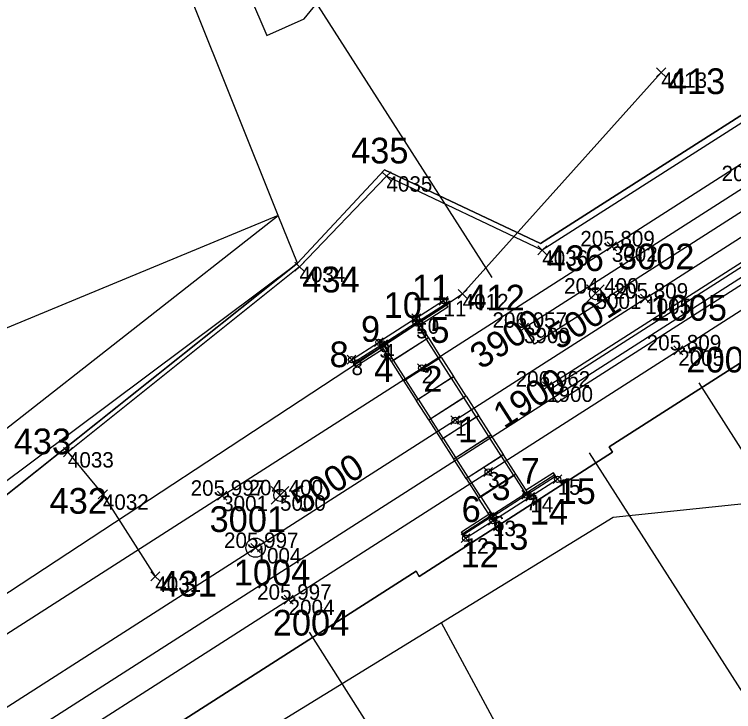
# Model space of a CAD drawing. Extents: x -752184 to -751416, y -1028299 to -1027836.
# Drawn here: x -751731.7 to -751675.7, y -1028071.5 to -1028017.3 of the extents above; entities that cross this region are included whole.
import ezdxf

# ---------------------------------------------------------------- set-up
doc = ezdxf.new("R2010")
doc.units = 0
for name, color, linetype in [('03_Staničení', 7, 'Continuous'), ('_SO 201 Nástupiště - Přesunutá', 7, 'Continuous'), ('SO 101 - spodní stavba', 7, 'Continuous'), ('SO 101 - vytyčovací body popis', 7, 'Continuous'), ('SO 101 - úpravy', 7, 'Continuous'), ('SO 101 Vytyčovací body', 7, 'Continuous'), ('SO 201 Osa koleje', 7, 'Continuous'), ('SO 201 Popisy', 7, 'Continuous'), ('SO 201 Staničení', 7, 'Continuous'), ('SO 201 Vytyčovací body', 7, 'Continuous'), ('SO 401 a 402 Přeložka SSZT a ČDT', 7, 'Continuous'), ('SO 401 a 402 Vytyčovací body', 7, 'Continuous'), ('SO 403 Přeložka SEE', 7, 'Continuous'), ('SO 403 Vytyčovací body', 7, 'Continuous'), ('Vrstva 53', 7, 'Continuous'), ('Vrstva 55', 7, 'Continuous'), ('Vrstva 60', 7, 'Continuous'), ('Vrstva 61', 7, 'Continuous'), ('Vrstva 63', 7, 'Continuous')]:
    doc.layers.add(name, color=color, linetype=linetype)

msp = doc.modelspace()

# ---------------------------------------------------------------- linework, layer by layer
at = {"layer": '03_Staničení'}
msp.add_circle((-751712.882, -1028058.77), 0.75, dxfattribs=at)
at = {"layer": '_SO 201 Nástupiště - Přesunutá'}
for p, q in [((-751690.026, -1028046.487), (-751567.868, -1027968.369)), ((-751567.232, -1027969.364), (-751689.391, -1028047.481)), ((-751652.107, -1028017.965), (-751691.168, -1028042.944)), ((-751691.987, -1028041.663), (-751674.155, -1028030.26)), ((-751691.168, -1028042.944), (-751691.987, -1028041.663)), ((-751689.391, -1028047.481), (-751690.188, -1028046.234))]:
    msp.add_line(p, q, dxfattribs=at)
msp.add_lwpolyline([(-751690.188, -1028046.234), (-751671.558, -1028034.321), (-751650.497, -1028020.852), (-751629.435, -1028007.384), (-751608.373, -1027993.915), (-751587.311, -1027980.447), (-751568.029, -1027968.117)], dxfattribs=at)
at = {"layer": 'SO 101 - spodní stavba'}
for p, q in [((-751698.251, -1028039.567), (-751700.357, -1028040.914)), ((-751698.089, -1028039.82), (-751700.195, -1028041.167)), ((-751700.141, -1028041.251), (-751698.035, -1028039.904)), ((-751698.035, -1028039.904), (-751698.251, -1028039.567)), ((-751700.357, -1028040.914), (-751700.141, -1028041.251)), ((-751703.144, -1028043.053), (-751705.25, -1028044.4)), ((-751702.146, -1028044.195), (-751702.314, -1028044.303)), ((-751702.314, -1028044.303), (-751701.355, -1028045.802)), ((-751701.187, -1028045.695), (-751702.146, -1028044.195)), ((-751701.355, -1028045.802), (-751701.187, -1028045.695)), ((-751701.176, -1028045.711), (-751701.344, -1028045.819)), ((-751701.344, -1028045.819), (-751700.385, -1028047.319)), ((-751700.217, -1028047.211), (-751701.176, -1028045.711)), ((-751700.385, -1028047.319), (-751700.217, -1028047.211)), ((-751700.206, -1028047.228), (-751700.375, -1028047.336)), ((-751699.247, -1028048.727), (-751700.206, -1028047.228)), ((-751700.375, -1028047.336), (-751699.415, -1028048.835)), ((-751699.415, -1028048.835), (-751699.247, -1028048.727)), ((-751699.236, -1028048.744), (-751699.405, -1028048.852)), ((-751699.405, -1028048.852), (-751698.446, -1028050.351)), ((-751698.277, -1028050.244), (-751699.236, -1028048.744)), ((-751698.446, -1028050.351), (-751698.277, -1028050.244)), ((-751698.266, -1028050.261), (-751698.435, -1028050.368)), ((-751698.435, -1028050.368), (-751697.476, -1028051.868)), ((-751697.307, -1028051.76), (-751698.266, -1028050.261)), ((-751697.476, -1028051.868), (-751697.307, -1028051.76)), ((-751697.297, -1028051.777), (-751697.465, -1028051.885)), ((-751696.337, -1028053.276), (-751697.297, -1028051.777)), ((-751697.465, -1028051.885), (-751696.506, -1028053.384)), ((-751696.506, -1028053.384), (-751696.337, -1028053.276)), ((-751696.327, -1028053.293), (-751696.495, -1028053.401)), ((-751696.495, -1028053.401), (-751695.536, -1028054.901)), ((-751695.368, -1028054.793), (-751696.327, -1028053.293)), ((-751689.587, -1028053.113), (-751691.693, -1028054.46)), ((-751691.639, -1028054.545), (-751689.533, -1028053.198)), ((-751691.477, -1028054.797), (-751689.371, -1028053.45)), ((-751689.371, -1028053.45), (-751689.587, -1028053.113)), ((-751691.714, -1028054.474), (-751694.62, -1028056.333)), ((-751691.498, -1028054.811), (-751691.714, -1028054.474)), ((-751691.693, -1028054.46), (-751691.477, -1028054.797)), ((-751695.536, -1028054.901), (-751695.368, -1028054.793)), ((-751694.405, -1028056.67), (-751691.498, -1028054.811)), ((-751694.641, -1028056.346), (-751696.747, -1028057.693)), ((-751694.587, -1028056.43), (-751696.693, -1028057.777)), ((-751696.532, -1028058.03), (-751694.426, -1028056.683)), ((-751694.426, -1028056.683), (-751694.641, -1028056.346)), ((-751694.62, -1028056.333), (-751694.405, -1028056.67)), ((-751696.747, -1028057.693), (-751696.532, -1028058.03))]:
    msp.add_line(p, q, dxfattribs=at)
for points in [[(-751698.035, -1028039.904), (-751697.927, -1028040.073), (-751700.054, -1028041.433)], [(-751703.284, -1028042.786), (-751703.069, -1028043.123), (-751700.162, -1028041.265), (-751700.378, -1028040.928), (-751703.284, -1028042.786)], [(-751700.216, -1028041.18), (-751700.385, -1028041.288), (-751702.954, -1028042.931), (-751703.122, -1028043.039)], [(-751702.157, -1028044.178), (-751699.587, -1028042.535), (-751700.385, -1028041.288)], [(-751699.587, -1028042.535), (-751699.419, -1028042.427), (-751700.054, -1028041.433), (-751700.162, -1028041.265)], [(-751705.411, -1028044.147), (-751703.305, -1028042.8), (-751703.09, -1028043.137), (-751705.196, -1028044.484), (-751705.411, -1028044.147)], [(-751701.187, -1028045.695), (-751698.617, -1028044.051), (-751699.576, -1028042.552), (-751702.146, -1028044.195)], [(-751698.617, -1028044.051), (-751698.449, -1028043.943), (-751699.408, -1028042.444), (-751699.576, -1028042.552)], [(-751705.196, -1028044.484), (-751705.088, -1028044.652), (-751702.961, -1028043.292)], [(-751703.122, -1028043.039), (-751702.961, -1028043.292), (-751702.325, -1028044.286), (-751702.157, -1028044.178), (-751702.954, -1028042.931)], [(-751698.607, -1028044.068), (-751698.438, -1028043.96), (-751697.479, -1028045.46), (-751697.647, -1028045.568)], [(-751700.217, -1028047.211), (-751697.647, -1028045.568), (-751698.607, -1028044.068), (-751701.176, -1028045.711)], [(-751699.247, -1028048.727), (-751696.678, -1028047.084), (-751697.637, -1028045.584), (-751700.206, -1028047.228)], [(-751697.637, -1028045.584), (-751697.468, -1028045.477), (-751696.509, -1028046.976), (-751696.678, -1028047.084)], [(-751698.277, -1028050.244), (-751695.708, -1028048.6), (-751696.667, -1028047.101), (-751699.236, -1028048.744)], [(-751696.667, -1028047.101), (-751696.498, -1028046.993), (-751695.539, -1028048.493), (-751695.708, -1028048.6)], [(-751697.307, -1028051.76), (-751694.738, -1028050.117), (-751695.697, -1028048.617), (-751698.266, -1028050.261)], [(-751695.697, -1028048.617), (-751695.528, -1028048.509), (-751694.569, -1028050.009), (-751694.738, -1028050.117)], [(-751694.727, -1028050.134), (-751694.559, -1028050.026), (-751693.6, -1028051.525), (-751693.768, -1028051.633)], [(-751696.337, -1028053.276), (-751693.768, -1028051.633), (-751694.727, -1028050.134), (-751697.297, -1028051.777)], [(-751696.327, -1028053.293), (-751693.757, -1028051.65), (-751692.798, -1028053.149), (-751695.368, -1028054.793)], [(-751692.798, -1028053.149), (-751692.63, -1028053.042), (-751693.589, -1028051.542), (-751693.757, -1028051.65)], [(-751695.357, -1028054.81), (-751692.787, -1028053.166), (-751691.828, -1028054.666)], [(-751691.714, -1028054.474), (-751691.821, -1028054.305), (-751692.619, -1028053.059), (-751692.787, -1028053.166)], [(-751689.587, -1028053.113), (-751689.694, -1028052.945), (-751691.821, -1028054.305)], [(-751694.566, -1028056.417), (-751694.398, -1028056.309), (-751691.828, -1028054.666), (-751691.66, -1028054.558)], [(-751694.62, -1028056.333), (-751694.728, -1028056.164), (-751695.525, -1028054.917), (-751695.357, -1028054.81), (-751694.398, -1028056.309)], [(-751696.747, -1028057.693), (-751696.855, -1028057.525), (-751694.728, -1028056.164)]]:
    msp.add_lwpolyline(points, dxfattribs=at)
at = {"layer": 'SO 101 - úpravy'}
for p, q in [((-751685.736, -1028038.323), (-751687.094, -1028039.681)), ((-751685.736, -1028039.681), (-751687.094, -1028038.323)), ((-751710.301, -1028054.016), (-751711.659, -1028055.374)), ((-751710.301, -1028055.374), (-751711.659, -1028054.016))]:
    msp.add_line(p, q, dxfattribs=at)
for centre in [(-751686.415, -1028039.002), (-751710.98, -1028054.695)]:
    msp.add_circle(centre, 0.48, dxfattribs=at)
at = {"layer": 'SO 101 Vytyčovací body'}
for p, q in [((-751697.912, -1028039.228), (-751698.59, -1028039.906)), ((-751697.912, -1028039.906), (-751698.59, -1028039.228)), ((-751700.039, -1028040.589), (-751700.717, -1028041.267)), ((-751700.039, -1028041.267), (-751700.717, -1028040.589)), ((-751700.045, -1028040.949), (-751700.724, -1028041.627)), ((-751700.045, -1028041.627), (-751700.724, -1028040.949)), ((-751702.945, -1028042.447), (-751703.623, -1028043.125)), ((-751702.945, -1028043.125), (-751703.623, -1028042.447)), ((-751702.615, -1028042.592), (-751703.293, -1028043.27)), ((-751702.615, -1028043.27), (-751703.293, -1028042.592)), ((-751705.072, -1028043.808), (-751705.75, -1028044.486)), ((-751705.072, -1028044.486), (-751705.75, -1028043.808)), ((-751699.612, -1028044.457), (-751700.29, -1028045.135)), ((-751699.612, -1028045.135), (-751700.29, -1028044.457)), ((-751697.014, -1028048.519), (-751697.692, -1028049.197)), ((-751697.014, -1028049.197), (-751697.692, -1028048.519)), ((-751694.439, -1028052.545), (-751695.117, -1028053.223)), ((-751694.439, -1028053.223), (-751695.117, -1028052.545)), ((-751689.032, -1028053.111), (-751689.71, -1028053.789)), ((-751689.032, -1028053.789), (-751689.71, -1028053.111)), ((-751691.489, -1028054.327), (-751692.167, -1028055.005)), ((-751691.489, -1028055.005), (-751692.167, -1028054.327)), ((-751691.159, -1028054.472), (-751691.837, -1028055.15)), ((-751691.159, -1028055.15), (-751691.837, -1028054.472)), ((-751694.059, -1028055.97), (-751694.737, -1028056.648)), ((-751694.059, -1028056.648), (-751694.737, -1028055.97)), ((-751694.066, -1028056.331), (-751694.744, -1028057.009)), ((-751694.066, -1028057.009), (-751694.744, -1028056.331)), ((-751696.193, -1028057.691), (-751696.871, -1028058.369)), ((-751696.193, -1028058.369), (-751696.871, -1028057.691))]:
    msp.add_line(p, q, dxfattribs=at)
for centre in [(-751698.251, -1028039.567), (-751700.385, -1028041.288), (-751700.378, -1028040.928), (-751703.284, -1028042.786), (-751702.954, -1028042.931), (-751705.411, -1028044.147), (-751699.951, -1028044.796), (-751697.353, -1028048.858), (-751694.778, -1028052.884), (-751689.371, -1028053.45), (-751691.828, -1028054.666), (-751691.498, -1028054.811), (-751694.398, -1028056.309), (-751694.405, -1028056.67), (-751696.532, -1028058.03)]:
    msp.add_circle(centre, 0.24, dxfattribs=at)
at = {"layer": 'SO 201 Osa koleje'}
for points in [[(-751812.029, -1028122.19), (-751769.905, -1028095.253), (-751753.825, -1028084.97), (-751748.27, -1028081.417), (-751742.714, -1028077.864), (-751712.886, -1028058.79), (-751682.557, -1028039.395), (-751557.444, -1027959.389), (-751515.321, -1027932.452)], [(-751811.363, -1028127.438), (-751769.239, -1028100.501), (-751746.594, -1028086.019), (-751741.482, -1028082.75), (-751736.37, -1028079.481), (-751710.311, -1028062.817), (-751679.982, -1028043.423), (-751627.749, -1028010.021), (-751616.695, -1028002.953), (-751577.545, -1027977.946)], [(-751782.496, -1028097.583), (-751740.372, -1028070.646), (-751715.482, -1028054.729), (-751685.153, -1028035.335), (-751653.819, -1028015.289), (-751611.692, -1027988.358)]]:
    msp.add_lwpolyline(points, dxfattribs=at)
at = {"layer": 'SO 201 Popisy'}
for p, q in [((-751740.473, -1027965.84), (-751694.492, -1028037.746)), ((-751631.497, -1028119.246), (-751678.366, -1028045.95)), ((-751652.477, -1028105.208), (-751686.886, -1028051.398)), ((-751688.361, -1028097.142), (-751708.695, -1028065.344))]:
    msp.add_line(p, q, dxfattribs=at)
at = {"layer": 'SO 201 Staničení'}
for points in [[(-751684.799, -1028035.689), (-751685.153, -1028035.335), (-751685.507, -1028034.981)], [(-751685.507, -1028035.689), (-751685.153, -1028035.335), (-751684.799, -1028034.981)], [(-751682.203, -1028039.749), (-751682.557, -1028039.395), (-751682.911, -1028039.041)], [(-751682.911, -1028039.749), (-751682.557, -1028039.395), (-751682.203, -1028039.041)], [(-751679.628, -1028043.777), (-751679.982, -1028043.423), (-751680.336, -1028043.069)], [(-751680.336, -1028043.777), (-751679.982, -1028043.423), (-751679.628, -1028043.069)], [(-751715.128, -1028055.083), (-751715.482, -1028054.729), (-751715.836, -1028054.375)], [(-751715.836, -1028055.083), (-751715.482, -1028054.729), (-751715.128, -1028054.375)], [(-751712.532, -1028059.144), (-751712.886, -1028058.79), (-751713.24, -1028058.436)], [(-751713.24, -1028059.144), (-751712.886, -1028058.79), (-751712.532, -1028058.436)], [(-751709.957, -1028063.171), (-751710.311, -1028062.817), (-751710.665, -1028062.463)], [(-751710.665, -1028063.171), (-751710.311, -1028062.817), (-751709.957, -1028062.463)]]:
    msp.add_lwpolyline(points, dxfattribs=at)
at = {"layer": 'SO 201 Vytyčovací body'}
for points in [[(-751691.633, -1028042.017), (-751691.987, -1028041.663), (-751692.341, -1028041.309)], [(-751692.341, -1028042.017), (-751691.987, -1028041.663), (-751691.633, -1028041.309)], [(-751689.834, -1028046.588), (-751690.188, -1028046.234), (-751690.542, -1028045.88)], [(-751690.542, -1028046.588), (-751690.188, -1028046.234), (-751689.834, -1028045.88)]]:
    msp.add_lwpolyline(points, dxfattribs=at)
at = {"layer": 'SO 401 a 402 Přeložka SSZT a ČDT'}
msp.add_lwpolyline([(-751662.307, -1028023.867), (-751665.138, -1028019.422), (-751690.565, -1028035.638), (-751702.692, -1028029.879), (-751709.463, -1028036.916), (-751727.486, -1028051.339), (-751724.767, -1028054.621), (-751720.688, -1028061.004)], dxfattribs=at)
at = {"layer": 'SO 401 a 402 Vytyčovací body'}
for points in [[(-751702.338, -1028030.233), (-751702.692, -1028029.879), (-751703.046, -1028029.525)], [(-751703.046, -1028030.233), (-751702.692, -1028029.879), (-751702.338, -1028029.525)], [(-751690.211, -1028035.992), (-751690.565, -1028035.638), (-751690.919, -1028035.284)], [(-751690.919, -1028035.992), (-751690.565, -1028035.638), (-751690.211, -1028035.284)], [(-751709.109, -1028037.27), (-751709.463, -1028036.916), (-751709.817, -1028036.562)], [(-751709.817, -1028037.27), (-751709.463, -1028036.916), (-751709.109, -1028036.562)], [(-751727.132, -1028051.693), (-751727.486, -1028051.339), (-751727.84, -1028050.985)], [(-751727.84, -1028051.693), (-751727.486, -1028051.339), (-751727.132, -1028050.985)], [(-751724.413, -1028054.975), (-751724.767, -1028054.621), (-751725.121, -1028054.267)], [(-751725.121, -1028054.975), (-751724.767, -1028054.621), (-751724.413, -1028054.267)], [(-751720.334, -1028061.358), (-751720.688, -1028061.004), (-751721.042, -1028060.65)], [(-751721.042, -1028061.358), (-751720.688, -1028061.004), (-751720.334, -1028060.65)]]:
    msp.add_lwpolyline(points, dxfattribs=at)
at = {"layer": 'SO 403 Přeložka SEE'}
msp.add_lwpolyline([(-751740.146, -1028067.489), (-751696.763, -1028039.03), (-751681.311, -1028021.803)], dxfattribs=at)
at = {"layer": 'SO 403 Vytyčovací body'}
for points in [[(-751680.957, -1028022.157), (-751681.311, -1028021.803), (-751681.665, -1028021.449)], [(-751681.665, -1028022.157), (-751681.311, -1028021.803), (-751680.957, -1028021.449)], [(-751696.409, -1028039.384), (-751696.763, -1028039.03), (-751697.117, -1028038.676)], [(-751697.117, -1028039.384), (-751696.763, -1028039.03), (-751696.409, -1028038.676)]]:
    msp.add_lwpolyline(points, dxfattribs=at)
at = {"layer": 'Vrstva 53'}
msp.add_line((-751685.1, -1028051.35), (-751700.15, -1028061), dxfattribs=at)
for points in [[(-751934.1, -1028186.19), (-751914.9, -1028176.41), (-751903.43, -1028170.23), (-751901.96, -1028169.44), (-751904.77, -1028166.14), (-751893.52, -1028163.47), (-751890.97, -1028163.13), (-751806.75, -1028109.29), (-751808.53, -1028106.05), (-751798.29, -1028099.68), (-751750.57, -1028069.21), (-751709.61, -1028036.63), (-751702.85, -1028029.39), (-751690.7, -1028035.11), (-751634.83, -1027999.42), (-751532.07, -1027933.64), (-751519.82, -1027926.47), (-751506.87, -1027919.58), (-751494.13, -1027913.25), (-751481.54, -1027906.54), (-751469.19, -1027899.14), (-751466.79, -1027897.6)], [(-751462.19, -1027906.18), (-751523.97, -1027945.11), (-751538.82, -1027960.28), (-751554.98, -1027970.94), (-751563.33, -1027976.45), (-751609.72, -1028006.9), (-751600.73, -1028021.25), (-751610.42, -1028027.79), (-751621, -1028034.71), (-751634.07, -1028041.54), (-751644.14, -1028025.2), (-751657.66, -1028033.82), (-751657.93, -1028033.4), (-751685.36, -1028050.92), (-751685.1, -1028051.35)], [(-751700.15, -1028061), (-751700.39, -1028060.59), (-751811.98, -1028131.93), (-751832.08, -1028145), (-751819.17, -1028158.43), (-751842.96, -1028162.99), (-751863.83, -1028164.81), (-751866.87, -1028174.68), (-751861.84, -1028173.32), (-751837.73, -1028166.78), (-751864.36, -1028191.47), (-751928.16, -1028233.3), (-751967.27, -1028248.1), (-751980.73, -1028255.56), (-751983.66, -1028257.34), (-752040.12, -1028287.87), (-752063.02, -1028298.92)]]:
    msp.add_lwpolyline(points, dxfattribs=at)
at = {"layer": 'Vrstva 55'}
for p, q in [((-751711.11, -1028032.94), (-751723.32, -1028002.47)), ((-751702.85, -1028029.39), (-751709.61, -1028036.63)), ((-751744.55, -1028059.1), (-751711.11, -1028032.94)), ((-751711.11, -1028032.94), (-751739.87, -1028044.82)), ((-751709.61, -1028036.63), (-751711.11, -1028032.94)), ((-751751.51, -1028067.92), (-751709.61, -1028036.63)), ((-751709.61, -1028036.63), (-751750.57, -1028069.21)), ((-751694.07, -1028072.66), (-751698.4, -1028064.61))]:
    msp.add_line(p, q, dxfattribs=at)
for points in [[(-751469.19, -1027899.14), (-751481.54, -1027906.54), (-751494.13, -1027913.25), (-751506.87, -1027919.58), (-751519.82, -1027926.47), (-751532.07, -1027933.64), (-751634.83, -1027999.42), (-751690.7, -1028035.11), (-751702.85, -1028029.39)], [(-751719.87, -1028000.62), (-751712.01, -1028018.94), (-751709.09, -1028017.63), (-751700.97, -1028007.7), (-751696.27, -1028003.7), (-751679.08, -1027991.59)], [(-751811.98, -1028131.93), (-751700.39, -1028060.59), (-751700.15, -1028061), (-751685.1, -1028051.35), (-751685.36, -1028050.92), (-751657.93, -1028033.4), (-751657.66, -1028033.82), (-751644.14, -1028025.2)], [(-751597.31, -1028027.06), (-751634.36, -1028051.12), (-751685.04, -1028056.42), (-751698.4, -1028064.61)], [(-751698.4, -1028064.61), (-751729.61, -1028083.77), (-751749, -1028095.68), (-751820.32, -1028139.23), (-751832.08, -1028145)]]:
    msp.add_lwpolyline(points, dxfattribs=at)
at = {"layer": 'Vrstva 60'}
for p, q in [((-751681.311, -1028021.803), (-751681.311, -1028021.803)), ((-751702.692, -1028029.879), (-751702.692, -1028029.879)), ((-751685.153, -1028035.335), (-751685.153, -1028035.335)), ((-751690.565, -1028035.638), (-751690.565, -1028035.638)), ((-751709.463, -1028036.916), (-751709.463, -1028036.916)), ((-751696.763, -1028039.03), (-751696.763, -1028039.03)), ((-751686.415, -1028039.002), (-751686.415, -1028039.002)), ((-751682.557, -1028039.395), (-751682.557, -1028039.395)), ((-751698.251, -1028039.567), (-751698.251, -1028039.567)), ((-751700.378, -1028040.928), (-751700.378, -1028040.928)), ((-751700.385, -1028041.288), (-751700.385, -1028041.288)), ((-751691.987, -1028041.663), (-751691.987, -1028041.663)), ((-751703.284, -1028042.786), (-751703.284, -1028042.786)), ((-751702.954, -1028042.931), (-751702.954, -1028042.931)), ((-751679.982, -1028043.423), (-751679.982, -1028043.423)), ((-751705.411, -1028044.147), (-751705.411, -1028044.147)), ((-751699.951, -1028044.796), (-751699.951, -1028044.796)), ((-751690.188, -1028046.234), (-751690.188, -1028046.234)), ((-751697.353, -1028048.858), (-751697.353, -1028048.858)), ((-751727.486, -1028051.339), (-751727.486, -1028051.339)), ((-751694.778, -1028052.884), (-751694.778, -1028052.884)), ((-751689.371, -1028053.45), (-751689.371, -1028053.45)), ((-751724.767, -1028054.621), (-751724.767, -1028054.621)), ((-751715.482, -1028054.729), (-751715.482, -1028054.729)), ((-751710.98, -1028054.695), (-751710.98, -1028054.695)), ((-751691.828, -1028054.666), (-751691.828, -1028054.666)), ((-751691.498, -1028054.811), (-751691.498, -1028054.811)), ((-751694.405, -1028056.67), (-751694.405, -1028056.67)), ((-751694.398, -1028056.309), (-751694.398, -1028056.309)), ((-751696.532, -1028058.03), (-751696.532, -1028058.03)), ((-751712.886, -1028058.79), (-751712.886, -1028058.79)), ((-751720.688, -1028061.004), (-751720.688, -1028061.004)), ((-751710.311, -1028062.817), (-751710.311, -1028062.817))]:
    msp.add_line(p, q, dxfattribs=at)
at = {"layer": 'Vrstva 63'}
msp.add_line((-751551.768, -1027958.946), (-751975.841, -1028229.997), dxfattribs=at)

# ---------------------------------------------------------------- texts
at = {"layer": 'SO 101 - vytyčovací body popis'}
for s, p in [('11', (-751700.702, -1028039.536)), ('10', (-751702.909, -1028040.897)), ('9', (-751704.677, -1028042.755)), ('5', (-751699.279, -1028042.84)), ('8', (-751707.119, -1028044.732)), ('4', (-751703.655, -1028045.885)), ('2', (-751699.816, -1028046.641)), ('1', (-751697.109, -1028050.58)), ('7', (-751692.24, -1028053.783)), ('3', (-751694.514, -1028055.073)), ('15', (-751689.379, -1028055.367)), ('6', (-751696.842, -1028056.772)), ('14', (-751691.537, -1028056.972)), ('13', (-751694.621, -1028058.936)), ('12', (-751696.925, -1028060.3))]:
    msp.add_text(s, height=2, dxfattribs=at).set_placement(p)
at = {"layer": 'SO 201 Vytyčovací body'}
for s, p in [('3002', (-751684.674, -1028037.116)), ('1005', (-751682.141, -1028041.115)), ('2005', (-751679.346, -1028045.144)), ('3001', (-751716.46, -1028057.548)), ('1004', (-751714.576, -1028061.698)), ('2004', (-751711.542, -1028065.606))]:
    msp.add_text(s, height=2, dxfattribs=at).set_placement(p)
for s, rotation, p in [('5001', 32.5984, (-751689.285, -1028043.436)), ('3900', 32.5976, (-751695.346, -1028044.953)), ('1900', 32.5976, (-751693.543, -1028049.553)), ('5000', 32.5984, (-751709.249, -1028056.212))]:
    msp.add_text(s, height=2, rotation=rotation, dxfattribs=at).set_placement(p)
at = {"layer": 'SO 401 a 402 Vytyčovací body'}
for s, p in [('435', (-751705.444, -1028028.887)), ('436', (-751690.238, -1028037.255)), ('434', (-751709.241, -1028038.916)), ('433', (-751731.706, -1028051.503)), ('432', (-751728.916, -1028056.129)), ('431', (-751720.351, -1028062.572))]:
    msp.add_text(s, height=2, dxfattribs=at).set_placement(p)
at = {"layer": 'SO 403 Vytyčovací body'}
for s, p in [('413', (-751680.788, -1028023.49)), ('412', (-751696.394, -1028040.32))]:
    msp.add_text(s, height=2, dxfattribs=at).set_placement(p)
at = {"layer": 'Vrstva 60'}
for s, p in [('4013', (-751681.311, -1028023.003)), ('4035', (-751702.692, -1028031.079)), ('3002', (-751685.153, -1028036.535)), ('4036', (-751690.565, -1028036.838)), ('4034', (-751709.463, -1028038.116)), ('4012', (-751696.763, -1028040.23)), ('5001', (-751686.415, -1028040.202)), ('1005', (-751682.557, -1028040.595)), ('11', (-751698.251, -1028040.767)), ('10', (-751700.378, -1028042.128)), ('5', (-751700.385, -1028042.488)), ('3900', (-751691.987, -1028042.863)), ('9', (-751703.284, -1028043.986)), ('4', (-751702.954, -1028044.131)), ('2005', (-751679.982, -1028044.623)), ('8', (-751705.411, -1028045.347)), ('2', (-751699.951, -1028045.996)), ('1900', (-751690.188, -1028047.434)), ('1', (-751697.353, -1028050.058)), ('4033', (-751727.486, -1028052.539)), ('3', (-751694.778, -1028054.084)), ('15', (-751689.371, -1028054.65)), ('4032', (-751724.767, -1028055.821)), ('3001', (-751715.482, -1028055.929)), ('5000', (-751710.98, -1028055.895)), ('7', (-751691.828, -1028055.866)), ('14', (-751691.498, -1028056.011)), ('6', (-751694.398, -1028057.509)), ('13', (-751694.405, -1028057.87)), ('12', (-751696.532, -1028059.23)), ('1004', (-751712.886, -1028059.99)), ('4031', (-751720.688, -1028062.204)), ('2004', (-751710.311, -1028064.017))]:
    msp.add_text(s, height=1.2, dxfattribs=at).set_placement(p)
at = {"layer": 'Vrstva 61'}
for s, p in [('205.946', (-751676.607, -1028030.26)), ('205.809', (-751687.607, -1028035.335)), ('204.400', (-751688.866, -1028039.002)), ('205.809', (-751685.011, -1028039.395)), ('206.057', (-751694.439, -1028041.663)), ('205.809', (-751682.436, -1028043.423)), ('206.062', (-751692.636, -1028046.234)), ('204.400', (-751713.431, -1028054.695)), ('205.997', (-751717.934, -1028054.729)), ('205.997', (-751715.338, -1028058.79)), ('205.997', (-751712.763, -1028062.817))]:
    msp.add_text(s, height=1.2, dxfattribs=at).set_placement(p)

doc.saveas('drawing.dxf')
